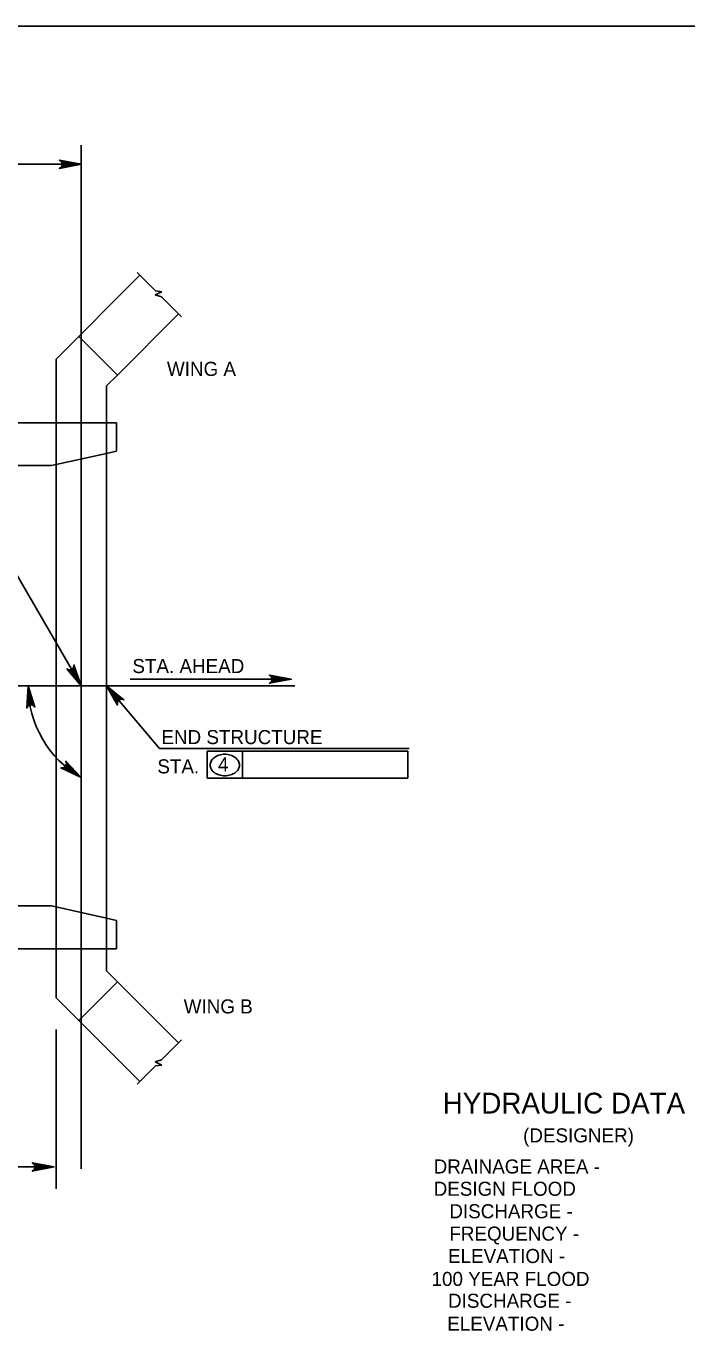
# Model space of a CAD drawing. Extents: x 638268 to 640277, y 295465 to 298435.
# Drawn here: x 638751 to 638891.9, y 297548.3 to 297826.5 of the extents above; entities that cross this region are included whole.
import ezdxf

# ---------------------------------------------------------------- set-up
doc = ezdxf.new("R2010")
doc.units = 0
for name, color, linetype in [('2', 7, 'Continuous'), ('3', 7, 'Continuous'), ('4', 7, 'Continuous')]:
    doc.layers.add(name, color=color, linetype=linetype)

msp = doc.modelspace()

# ---------------------------------------------------------------- linework, layer by layer
at = {"layer": '2'}
for p, q in [((638475.46, 297826.46), (639261.46, 297826.46)), ((638757.42, 297755.46), (638775.29, 297773.33)), ((638770.49, 297752.07), (638783.52, 297765.1)), ((638770.49, 297752.07), (638762.26, 297760.3)), ((638757.42, 297755.46), (638757.42, 297741.89)), ((638768.19, 297749.77), (638770.49, 297752.07)), ((638768.19, 297749.77), (638768.19, 297741.89)), ((638770.31, 297741.89), (638738.57, 297741.89)), ((638757.42, 297629.62), (638757.42, 297741.89)), ((638768.19, 297629.62), (638768.19, 297741.89)), ((638770.31, 297735.86), (638770.31, 297741.89)), ((638768.14, 297735.37), (638756.47, 297732.77)), ((638770.31, 297735.86), (638768.14, 297735.37)), ((638770.31, 297735.86), (638768.14, 297735.37)), ((638603.59, 297732.77), (638756.47, 297732.77)), ((638603.59, 297638.9), (638756.47, 297638.9)), ((638768.14, 297636.29), (638756.47, 297638.9)), ((638770.31, 297635.8), (638768.14, 297636.29)), ((638770.31, 297635.8), (638768.14, 297636.29)), ((638770.31, 297629.77), (638770.31, 297635.8)), ((638770.31, 297629.77), (638738.57, 297629.77)), ((638757.42, 297619.35), (638757.42, 297629.62)), ((638768.19, 297625.04), (638768.19, 297629.62)), ((638768.19, 297625.04), (638783.52, 297609.71)), ((638770.49, 297622.73), (638762.26, 297614.51)), ((638757.42, 297619.35), (638775.29, 297601.48))]:
    msp.add_line(p, q, dxfattribs=at)
at = {"layer": '3'}
for p, q in [((638762.8, 297582.86), (638762.8, 297801.11)), ((638778.61, 297770), (638774.7, 297773.91)), ((638779.97, 297769.84), (638778.57, 297769.14)), ((638778.57, 297769.14), (638779.88, 297768.73)), ((638778.61, 297770), (638779.97, 297769.84)), ((638784.15, 297764.46), (638779.88, 297768.73)), ((638784.15, 297610.35), (638779.88, 297606.08)), ((638778.61, 297604.81), (638774.7, 297600.9)), ((638778.57, 297605.67), (638779.88, 297606.08)), ((638779.97, 297604.97), (638778.57, 297605.67)), ((638778.61, 297604.81), (638779.97, 297604.97))]:
    msp.add_line(p, q, dxfattribs=at)
at = {"layer": '4'}
for p, q in [((638566.62, 297797), (638762.8, 297797)), ((638762.8, 297685.83), (638748.74, 297710.01)), ((638523.29, 297685.83), (638808.3, 297685.83)), ((638768.19, 297685.83), (638779.49, 297672.49)), ((638807.54, 297687.23), (638773.18, 297687.23)), ((638779.49, 297672.49), (638832.67, 297672.49)), ((638789.59, 297671.87), (638797.17, 297671.87)), ((638789.59, 297666.11), (638789.59, 297671.87)), ((638797.17, 297666.11), (638797.17, 297671.87)), ((638797.17, 297671.87), (638832.35, 297671.87)), ((638832.35, 297671.87), (638832.35, 297666.11)), ((638789.59, 297666.11), (638832.35, 297666.11)), ((638757.42, 297612.54), (638757.42, 297578.62)), ((638572.01, 297583.28), (638757, 297583.28))]:
    msp.add_line(p, q, dxfattribs=at)
for points in [[(638762.8, 297797), (638758.14, 297796.12), (638758.5, 297796.37), (638758.69, 297796.68), (638758.74, 297797), (638758.69, 297797.31), (638758.5, 297797.62), (638758.14, 297797.87), (638762.8, 297797), (638758.5, 297797.62), (638758.69, 297797.31), (638762.8, 297797), (638758.74, 297797), (638758.69, 297796.68), (638762.8, 297797), (638758.5, 297796.37)], [(638762.8, 297685.83), (638759.71, 297689.42), (638760.1, 297689.23), (638760.46, 297689.23), (638760.76, 297689.34), (638761, 297689.55), (638761.18, 297689.86), (638761.22, 297690.3), (638762.8, 297685.83), (638761.18, 297689.86), (638761, 297689.55), (638762.8, 297685.83), (638760.76, 297689.34), (638760.46, 297689.23), (638762.8, 297685.83), (638760.1, 297689.23)], [(638807.54, 297687.23), (638802.88, 297686.36), (638803.24, 297686.61), (638803.43, 297686.92), (638803.48, 297687.23), (638803.43, 297687.55), (638803.24, 297687.86), (638802.88, 297688.11), (638807.54, 297687.23), (638803.24, 297687.86), (638803.43, 297687.55), (638807.54, 297687.23), (638803.48, 297687.23), (638803.43, 297686.92), (638807.54, 297687.23), (638803.24, 297686.61)], [(638751.47, 297685.83), (638752.9, 297681.31), (638752.61, 297681.64), (638752.28, 297681.78), (638751.96, 297681.8), (638751.66, 297681.71), (638751.37, 297681.48), (638751.17, 297681.1), (638751.47, 297685.83), (638751.37, 297681.48), (638751.66, 297681.71), (638751.47, 297685.83), (638751.96, 297681.8), (638752.28, 297681.78), (638751.47, 297685.83), (638752.61, 297681.64)], [(638768.19, 297685.83), (638771.86, 297682.84), (638771.44, 297682.95), (638771.09, 297682.89), (638770.81, 297682.73), (638770.61, 297682.49), (638770.49, 297682.15), (638770.53, 297681.71), (638768.19, 297685.83), (638770.49, 297682.15), (638770.61, 297682.49), (638768.19, 297685.83), (638770.81, 297682.73), (638771.09, 297682.89), (638768.19, 297685.83), (638771.44, 297682.95)], [(638762.74, 297666.31), (638758.45, 297668.33), (638758.88, 297668.32), (638759.21, 297668.47), (638759.44, 297668.69), (638759.58, 297668.97), (638759.61, 297669.33), (638759.47, 297669.75), (638762.74, 297666.31), (638759.61, 297669.33), (638759.58, 297668.97), (638762.74, 297666.31), (638759.44, 297668.69), (638759.21, 297668.47), (638762.74, 297666.31), (638758.88, 297668.32)], [(638756.99, 297583.28), (638752.33, 297582.4), (638752.69, 297582.65), (638752.88, 297582.96), (638752.93, 297583.28), (638752.88, 297583.59), (638752.69, 297583.9), (638752.33, 297584.15), (638756.99, 297583.28), (638752.69, 297583.9), (638752.88, 297583.59), (638756.99, 297583.28), (638752.93, 297583.28), (638752.88, 297582.96), (638756.99, 297583.28), (638752.69, 297582.65)]]:
    msp.add_lwpolyline(points, dxfattribs=at)
for centre, radius, start, end in [((638774.01, 297685.83), 22.54, 179.9993, 239.9995), ((638793.08, 297667.96), 3.23, 106.9552, 126.3544), ((638793.37, 297667.02), 4.22, 90, 106.9552), ((638793.37, 297667.02), 4.22, 73.0448, 90), ((638793.66, 297667.96), 3.23, 53.6456, 73.0448), ((638791.97, 297668.94), 1.71, 150.6308, 180), ((638791.97, 297668.94), 1.71, 180, 209.3692), ((638792.64, 297668.56), 2.49, 126.3544, 150.6308), ((638794.1, 297668.56), 2.49, 29.3692, 53.6456), ((638794.78, 297668.94), 1.71, 0, 29.3692), ((638794.78, 297668.94), 1.71, 330.6308, 0), ((638792.64, 297669.32), 2.49, 209.3692, 233.6456), ((638793.08, 297669.92), 3.23, 233.6456, 253.0448), ((638793.37, 297670.87), 4.22, 253.0448, 270), ((638793.37, 297670.87), 4.22, 270, 286.9552), ((638793.66, 297669.92), 3.23, 286.9552, 306.3544), ((638794.1, 297669.32), 2.49, 306.3544, 330.6308)]:
    msp.add_arc(centre, radius, start, end, dxfattribs=at)

# ---------------------------------------------------------------- texts
for s, height, p in [('WING A', 3, (638781.05, 297751.89)), ('STA. AHEAD', 3, (638773.68, 297688.54)), ('END STRUCTURE', 3, (638779.87, 297673.4)), ('STA.', 3, (638779, 297667.16)), ('4', 3, (638791.92, 297667.59)), ('WING B', 3, (638784.62, 297615.99)), ('HYDRAULIC DATA', 4.4292, (638839.81, 297594.66)), ('(DESIGNER)', 3, (638856.95, 297588.5)), ('DRAINAGE AREA - ', 3, (638837.89, 297581.87)), ('DESIGN FLOOD  ', 3, (638837.89, 297577.12)), ('   DISCHARGE - ', 3, (638837.89, 297572.33)), ('   FREQUENCY - ', 3, (638837.89, 297567.56)), ('   ELEVATION - ', 3, (638837.61, 297562.79)), ('100 YEAR FLOOD', 3, (638837.44, 297557.9)), ('   DISCHARGE - ', 3, (638837.61, 297553.25)), ('   ELEVATION - ', 3, (638837.44, 297548.36))]:
    msp.add_text(s, height=height, dxfattribs=at).set_placement(p)

doc.saveas('drawing.dxf')
